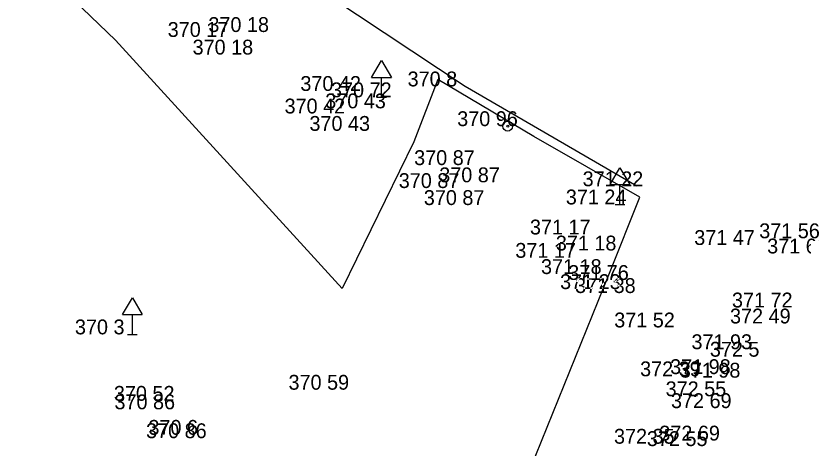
# Model space of a CAD drawing. Extents: x -688316 to -688024, y -973785 to -973591.
# Drawn here: x -688092.11 to -688052.25, y -973741.03 to -973719.16 of the extents above; entities that cross this region are included whole.
import ezdxf

# ---------------------------------------------------------------- set-up
doc = ezdxf.new("R2010")
doc.units = 0
for name, color, linetype in [('Vrstva 10', 7, 'Continuous'), ('Vrstva 25', 7, 'Continuous'), ('Vrstva 3', 7, 'Continuous'), ('Vrstva 34', 7, 'Continuous')]:
    doc.layers.add(name, color=color, linetype=linetype)

# ---------------------------------------------------------------- blocks, each defined once
blk = doc.blocks.new('DZ')
at = {"layer": 'Vrstva 34'}
for p, q in [((-5, 10), (0, 18.5)), ((0, 18.5), (5, 10)), ((-5, 10), (5, 10)), ((0, 0), (0, 10)), ((-2.49, 0), (2.49, 0))]:
    blk.add_line(p, q, dxfattribs=at)
blk = doc.blocks.new('SPMR')
at = {"layer": 'Vrstva 25'}
for radius in [2.5, 0.5]:
    blk.add_circle((0, 0), radius, dxfattribs=at)

msp = doc.modelspace()

# ---------------------------------------------------------------- linework, layer by layer
at = {"layer": 'Vrstva 10'}
for p, q in [((-688069.37, -973722.73), (-688077.23, -973717.52)), ((-688060.68, -973727.78), (-688069.37, -973722.73))]:
    msp.add_line(p, q, dxfattribs=at)
at = {"layer": 'Vrstva 3'}
for points in [[(-688071.97, -973725.53), (-688075.592, -973732.953), (-688087.068, -973720.398), (-688092.114, -973715.537), (-688090.26, -973713.47)], [(-688071.97, -973725.53), (-688075.592, -973732.953), (-688087.068, -973720.398), (-688092.114, -973715.537), (-688090.26, -973713.47)], [(-688071.97, -973725.53), (-688075.592, -973732.953), (-688087.068, -973720.398), (-688092.114, -973715.537), (-688090.26, -973713.47)], [(-688071.97, -973725.53), (-688075.592, -973732.953), (-688087.068, -973720.398), (-688092.114, -973715.537), (-688090.26, -973713.47)], [(-688066.073, -973742.092), (-688062.05, -973732.17), (-688060.52, -973728.33), (-688065.89, -973725.27), (-688070.75, -973722.38), (-688071.97, -973725.53)], [(-688066.073, -973742.092), (-688062.05, -973732.17), (-688060.52, -973728.33), (-688065.89, -973725.27), (-688070.75, -973722.38), (-688071.97, -973725.53)], [(-688066.073, -973742.092), (-688062.05, -973732.17), (-688060.52, -973728.33), (-688065.89, -973725.27), (-688070.75, -973722.38), (-688071.97, -973725.53)], [(-688066.073, -973742.092), (-688062.05, -973732.17), (-688060.52, -973728.33), (-688065.89, -973725.27), (-688070.75, -973722.38), (-688071.97, -973725.53)]]:
    msp.add_lwpolyline(points, dxfattribs=at)

# ---------------------------------------------------------------- block references
at = {"layer": 'Vrstva 25', "xscale": 0.1, "yscale": 0.10000000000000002}
msp.add_blockref('SPMR', (-688067.21, -973724.74), dxfattribs=at)
at = {"layer": 'Vrstva 34', "xscale": 0.1, "yscale": 0.10000000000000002}
for p in [(-688073.6, -973723.28), (-688073.6, -973723.28), (-688073.6, -973723.28), (-688073.6, -973723.28), (-688061.53, -973728.7), (-688061.53, -973728.7), (-688086.21, -973735.27), (-688086.21, -973735.27)]:
    msp.add_blockref('DZ', p, dxfattribs=at)

# ---------------------------------------------------------------- texts
at = {"layer": 'Vrstva 3'}
for s, p in [('370 18 ', (-688082.363, -973719.98)), ('370 18 ', (-688082.363, -973719.98)), ('370 18 ', (-688082.363, -973719.98)), ('370 18 ', (-688082.363, -973719.98)), ('370 18 ', (-688082.363, -973719.98)), ('370 18 ', (-688082.363, -973719.98)), ('370 18 ', (-688082.363, -973719.98)), ('370 17 ', (-688084.423, -973720.23)), ('370 17 ', (-688084.423, -973720.23)), ('370 17 ', (-688084.423, -973720.23)), ('370 17 ', (-688084.423, -973720.23)), ('370 17 ', (-688084.423, -973720.23)), ('370 17 ', (-688084.423, -973720.23)), ('370 17 ', (-688084.423, -973720.23)), ('370 18 ', (-688083.163, -973721.12)), ('370 18 ', (-688083.163, -973721.12)), ('370 18 ', (-688083.163, -973721.12)), ('370 18 ', (-688083.163, -973721.12)), ('370 18 ', (-688083.163, -973721.12)), ('370 18 ', (-688083.163, -973721.12)), ('370 18 ', (-688083.163, -973721.12)), ('370 8  ', (-688072.278, -973722.73)), ('370 8  ', (-688072.278, -973722.73)), ('370 8  ', (-688072.278, -973722.73)), ('370 8  ', (-688072.278, -973722.73)), ('370 8  ', (-688072.278, -973722.73)), ('370 8  ', (-688072.278, -973722.73)), ('370 8  ', (-688072.278, -973722.73)), ('370 42 ', (-688077.707, -973722.96)), ('370 42 ', (-688077.707, -973722.96)), ('370 42 ', (-688077.707, -973722.96)), ('370 42 ', (-688077.707, -973722.96)), ('370 42 ', (-688077.707, -973722.96)), ('370 42 ', (-688077.707, -973722.96)), ('370 42 ', (-688077.707, -973722.96)), ('370 72 ', (-688076.157, -973723.28)), ('370 72 ', (-688076.157, -973723.28)), ('370 72 ', (-688076.157, -973723.28)), ('370 72 ', (-688076.157, -973723.28)), ('370 72 ', (-688076.157, -973723.28)), ('370 72 ', (-688076.157, -973723.28)), ('370 72 ', (-688076.157, -973723.28)), ('370 43 ', (-688076.447, -973723.84)), ('370 43 ', (-688076.447, -973723.84)), ('370 43 ', (-688076.447, -973723.84)), ('370 43 ', (-688076.447, -973723.84)), ('370 43 ', (-688076.447, -973723.84)), ('370 43 ', (-688076.447, -973723.84)), ('370 43 ', (-688076.447, -973723.84)), ('370 42 ', (-688078.507, -973724.1)), ('370 42 ', (-688078.507, -973724.1)), ('370 42 ', (-688078.507, -973724.1)), ('370 42 ', (-688078.507, -973724.1)), ('370 42 ', (-688078.507, -973724.1)), ('370 42 ', (-688078.507, -973724.1)), ('370 42 ', (-688078.507, -973724.1)), ('370 96 ', (-688069.767, -973724.74)), ('370 96 ', (-688069.767, -973724.74)), ('370 96 ', (-688069.767, -973724.74)), ('370 96 ', (-688069.767, -973724.74)), ('370 96 ', (-688069.767, -973724.74)), ('370 96 ', (-688069.767, -973724.74)), ('370 96 ', (-688069.767, -973724.74)), ('370 43 ', (-688077.247, -973724.98)), ('370 43 ', (-688077.247, -973724.98)), ('370 43 ', (-688077.247, -973724.98)), ('370 43 ', (-688077.247, -973724.98)), ('370 43 ', (-688077.247, -973724.98)), ('370 43 ', (-688077.247, -973724.98)), ('370 43 ', (-688077.247, -973724.98)), ('370 87 ', (-688071.947, -973726.71)), ('370 87 ', (-688071.947, -973726.71)), ('370 87 ', (-688071.947, -973726.71)), ('370 87 ', (-688071.947, -973726.71)), ('370 87 ', (-688071.947, -973726.71)), ('370 87 ', (-688071.947, -973726.71)), ('370 87 ', (-688071.947, -973726.71)), ('370 87 ', (-688070.677, -973727.58)), ('370 87 ', (-688070.677, -973727.58)), ('370 87 ', (-688070.677, -973727.58)), ('370 87 ', (-688070.677, -973727.58)), ('370 87 ', (-688070.677, -973727.58)), ('370 87 ', (-688070.677, -973727.58)), ('370 87 ', (-688070.677, -973727.58)), ('370 87 ', (-688072.727, -973727.87)), ('370 87 ', (-688072.727, -973727.87)), ('370 87 ', (-688072.727, -973727.87)), ('370 87 ', (-688072.727, -973727.87)), ('370 87 ', (-688072.727, -973727.87)), ('370 87 ', (-688072.727, -973727.87)), ('370 87 ', (-688072.727, -973727.87)), ('371 22 ', (-688063.419, -973727.78)), ('371 22 ', (-688063.419, -973727.78)), ('371 22 ', (-688063.419, -973727.78)), ('371 22 ', (-688063.419, -973727.78)), ('371 22 ', (-688063.419, -973727.78)), ('371 22 ', (-688063.419, -973727.78)), ('371 22 ', (-688063.419, -973727.78)), ('370 87 ', (-688071.457, -973728.73)), ('370 87 ', (-688071.457, -973728.73)), ('370 87 ', (-688071.457, -973728.73)), ('370 87 ', (-688071.457, -973728.73)), ('370 87 ', (-688071.457, -973728.73)), ('370 87 ', (-688071.457, -973728.73)), ('370 87 ', (-688071.457, -973728.73)), ('371 24 ', (-688064.269, -973728.7)), ('371 24 ', (-688064.269, -973728.7)), ('371 24 ', (-688064.269, -973728.7)), ('371 24 ', (-688064.269, -973728.7)), ('371 24 ', (-688064.269, -973728.7)), ('371 24 ', (-688064.269, -973728.7)), ('371 24 ', (-688064.269, -973728.7)), ('371 17 ', (-688066.085, -973730.22)), ('371 17 ', (-688066.085, -973730.22)), ('371 17 ', (-688066.085, -973730.22)), ('371 17 ', (-688066.085, -973730.22)), ('371 17 ', (-688066.085, -973730.22)), ('371 17 ', (-688066.085, -973730.22)), ('371 17 ', (-688066.085, -973730.22)), ('371 47 ', (-688057.769, -973730.75)), ('371 47 ', (-688057.769, -973730.75)), ('371 47 ', (-688057.769, -973730.75)), ('371 47 ', (-688057.769, -973730.75)), ('371 47 ', (-688057.769, -973730.75)), ('371 47 ', (-688057.769, -973730.75)), ('371 47 ', (-688057.769, -973730.75)), ('371 56 ', (-688054.479, -973730.41)), ('371 56 ', (-688054.479, -973730.41)), ('371 56 ', (-688054.479, -973730.41)), ('371 56 ', (-688054.479, -973730.41)), ('371 56 ', (-688054.479, -973730.41)), ('371 56 ', (-688054.479, -973730.41)), ('371 56 ', (-688054.479, -973730.41)), ('371 18 ', (-688064.775, -973731.03)), ('371 18 ', (-688064.775, -973731.03)), ('371 18 ', (-688064.775, -973731.03)), ('371 18 ', (-688064.775, -973731.03)), ('371 18 ', (-688064.775, -973731.03)), ('371 18 ', (-688064.775, -973731.03)), ('371 18 ', (-688064.775, -973731.03)), ('371 17 ', (-688066.825, -973731.4)), ('371 17 ', (-688066.825, -973731.4)), ('371 17 ', (-688066.825, -973731.4)), ('371 17 ', (-688066.825, -973731.4)), ('371 17 ', (-688066.825, -973731.4)), ('371 17 ', (-688066.825, -973731.4)), ('371 17 ', (-688066.825, -973731.4)), ('371 66 ', (-688054.078, -973731.18)), ('371 66 ', (-688054.078, -973731.18)), ('371 66 ', (-688054.078, -973731.18)), ('371 66 ', (-688054.078, -973731.18)), ('371 66 ', (-688054.078, -973731.18)), ('371 66 ', (-688054.078, -973731.18)), ('371 66 ', (-688054.078, -973731.18)), ('371 18 ', (-688065.525, -973732.22)), ('371 18 ', (-688065.525, -973732.22)), ('371 18 ', (-688065.525, -973732.22)), ('371 18 ', (-688065.525, -973732.22)), ('371 18 ', (-688065.525, -973732.22)), ('371 18 ', (-688065.525, -973732.22)), ('371 18 ', (-688065.525, -973732.22)), ('371 76 ', (-688064.149, -973732.52)), ('371 76 ', (-688064.149, -973732.52)), ('371 76 ', (-688064.149, -973732.52)), ('371 76 ', (-688064.149, -973732.52)), ('371 76 ', (-688064.149, -973732.52)), ('371 76 ', (-688064.149, -973732.52)), ('371 76 ', (-688064.149, -973732.52)), ('371 23 ', (-688064.559, -973732.98)), ('371 23 ', (-688064.559, -973732.98)), ('371 23 ', (-688064.559, -973732.98)), ('371 23 ', (-688064.559, -973732.98)), ('371 23 ', (-688064.559, -973732.98)), ('371 23 ', (-688064.559, -973732.98)), ('371 23 ', (-688064.559, -973732.98)), ('371 38 ', (-688063.801, -973733.18)), ('371 38 ', (-688063.801, -973733.18)), ('371 38 ', (-688063.801, -973733.18)), ('371 38 ', (-688063.801, -973733.18)), ('371 38 ', (-688063.801, -973733.18)), ('371 38 ', (-688063.801, -973733.18)), ('371 38 ', (-688063.801, -973733.18)), ('371 72 ', (-688055.859, -973733.91)), ('371 72 ', (-688055.859, -973733.91)), ('371 72 ', (-688055.859, -973733.91)), ('371 72 ', (-688055.859, -973733.91)), ('371 72 ', (-688055.859, -973733.91)), ('371 72 ', (-688055.859, -973733.91)), ('371 72 ', (-688055.859, -973733.91)), ('372 49 ', (-688055.957, -973734.72)), ('372 49 ', (-688055.957, -973734.72)), ('372 49 ', (-688055.957, -973734.72)), ('372 49 ', (-688055.957, -973734.72)), ('372 49 ', (-688055.957, -973734.72)), ('372 49 ', (-688055.957, -973734.72)), ('372 49 ', (-688055.957, -973734.72)), ('371 52 ', (-688061.819, -973734.92)), ('371 52 ', (-688061.819, -973734.92)), ('371 52 ', (-688061.819, -973734.92)), ('371 52 ', (-688061.819, -973734.92)), ('371 52 ', (-688061.819, -973734.92)), ('371 52 ', (-688061.819, -973734.92)), ('371 52 ', (-688061.819, -973734.92)), ('370 3  ', (-688089.118, -973735.27)), ('370 3  ', (-688089.118, -973735.27)), ('370 3  ', (-688089.118, -973735.27)), ('370 3  ', (-688089.118, -973735.27)), ('370 3  ', (-688089.118, -973735.27)), ('370 3  ', (-688089.118, -973735.27)), ('370 3  ', (-688089.118, -973735.27)), ('371 93 ', (-688057.909, -973736.02)), ('371 93 ', (-688057.909, -973736.02)), ('371 93 ', (-688057.909, -973736.02)), ('371 93 ', (-688057.909, -973736.02)), ('371 93 ', (-688057.909, -973736.02)), ('371 93 ', (-688057.909, -973736.02)), ('371 93 ', (-688057.909, -973736.02)), ('372 5  ', (-688056.978, -973736.4)), ('372 5  ', (-688056.978, -973736.4)), ('372 5  ', (-688056.978, -973736.4)), ('372 5  ', (-688056.978, -973736.4)), ('372 5  ', (-688056.978, -973736.4)), ('372 5  ', (-688056.978, -973736.4)), ('372 5  ', (-688056.978, -973736.4)), ('372 39 ', (-688060.509, -973737.39)), ('372 39 ', (-688060.509, -973737.39)), ('372 39 ', (-688060.509, -973737.39)), ('372 39 ', (-688060.509, -973737.39)), ('372 39 ', (-688060.509, -973737.39)), ('372 39 ', (-688060.509, -973737.39)), ('372 39 ', (-688060.509, -973737.39)), ('371 98 ', (-688058.989, -973737.28)), ('371 98 ', (-688058.989, -973737.28)), ('371 98 ', (-688058.989, -973737.28)), ('371 98 ', (-688058.989, -973737.28)), ('371 98 ', (-688058.989, -973737.28)), ('371 98 ', (-688058.989, -973737.28)), ('371 98 ', (-688058.989, -973737.28)), ('371 98 ', (-688058.499, -973737.46)), ('371 98 ', (-688058.499, -973737.46)), ('371 98 ', (-688058.499, -973737.46)), ('371 98 ', (-688058.499, -973737.46)), ('371 98 ', (-688058.499, -973737.46)), ('371 98 ', (-688058.499, -973737.46)), ('371 98 ', (-688058.499, -973737.46)), ('370 59 ', (-688078.307, -973738.07)), ('370 59 ', (-688078.307, -973738.07)), ('370 59 ', (-688078.307, -973738.07)), ('370 59 ', (-688078.307, -973738.07)), ('370 59 ', (-688078.307, -973738.07)), ('370 59 ', (-688078.307, -973738.07)), ('370 59 ', (-688078.307, -973738.07)), ('370 52 ', (-688087.147, -973738.63)), ('370 52 ', (-688087.147, -973738.63)), ('370 52 ', (-688087.147, -973738.63)), ('370 52 ', (-688087.147, -973738.63)), ('370 52 ', (-688087.147, -973738.63)), ('370 52 ', (-688087.147, -973738.63)), ('370 52 ', (-688087.147, -973738.63)), ('372 55 ', (-688059.217, -973738.4)), ('372 55 ', (-688059.217, -973738.4)), ('372 55 ', (-688059.217, -973738.4)), ('372 55 ', (-688059.217, -973738.4)), ('372 55 ', (-688059.217, -973738.4)), ('372 55 ', (-688059.217, -973738.4)), ('372 55 ', (-688059.217, -973738.4)), ('370 86 ', (-688087.117, -973739.06)), ('370 86 ', (-688087.117, -973739.06)), ('370 86 ', (-688087.117, -973739.06)), ('370 86 ', (-688087.117, -973739.06)), ('370 86 ', (-688087.117, -973739.06)), ('370 86 ', (-688087.117, -973739.06)), ('370 86 ', (-688087.117, -973739.06)), ('372 69 ', (-688058.946, -973739)), ('372 69 ', (-688058.946, -973739)), ('372 69 ', (-688058.946, -973739)), ('372 69 ', (-688058.946, -973739)), ('372 69 ', (-688058.946, -973739)), ('372 69 ', (-688058.946, -973739)), ('372 69 ', (-688058.946, -973739)), ('370 86 ', (-688085.517, -973740.52)), ('370 86 ', (-688085.517, -973740.52)), ('370 86 ', (-688085.517, -973740.52)), ('370 86 ', (-688085.517, -973740.52)), ('370 86 ', (-688085.517, -973740.52)), ('370 86 ', (-688085.517, -973740.52)), ('370 86 ', (-688085.517, -973740.52)), ('370 6  ', (-688085.398, -973740.35)), ('370 6  ', (-688085.398, -973740.35)), ('370 6  ', (-688085.398, -973740.35)), ('370 6  ', (-688085.398, -973740.35)), ('370 6  ', (-688085.398, -973740.35)), ('370 6  ', (-688085.398, -973740.35)), ('370 6  ', (-688085.398, -973740.35)), ('372 69 ', (-688059.536, -973740.64)), ('372 69 ', (-688059.536, -973740.64)), ('372 69 ', (-688059.536, -973740.64)), ('372 69 ', (-688059.536, -973740.64)), ('372 69 ', (-688059.536, -973740.64)), ('372 69 ', (-688059.536, -973740.64)), ('372 69 ', (-688059.536, -973740.64)), ('372 35 ', (-688061.829, -973740.8)), ('372 35 ', (-688061.829, -973740.8)), ('372 35 ', (-688061.829, -973740.8)), ('372 35 ', (-688061.829, -973740.8)), ('372 35 ', (-688061.829, -973740.8)), ('372 35 ', (-688061.829, -973740.8)), ('372 35 ', (-688061.829, -973740.8)), ('372 55 ', (-688060.167, -973740.92)), ('372 55 ', (-688060.167, -973740.92)), ('372 55 ', (-688060.167, -973740.92)), ('372 55 ', (-688060.167, -973740.92)), ('372 55 ', (-688060.167, -973740.92)), ('372 55 ', (-688060.167, -973740.92)), ('372 55 ', (-688060.167, -973740.92))]:
    msp.add_text(s, height=0.75, dxfattribs=at).set_placement(p)

doc.saveas('drawing.dxf')
